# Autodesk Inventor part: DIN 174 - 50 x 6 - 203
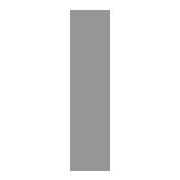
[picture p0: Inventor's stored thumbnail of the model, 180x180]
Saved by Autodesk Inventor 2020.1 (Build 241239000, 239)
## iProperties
IsCustomPart: 1
_CCFamilyMember: 200
_CCFamilyDisplayName: DIN EN 10278 - Flachstahl
_FrameMemberDoc: Frame Member File
_Version: 15.0.0
_GetPNFromCC: 1
Created: 2019-01
Part Number: DIN 174 - 50 x 6 - 203
Material: Stahl, weich
Description: Flachstahl
Document SubType Name: Modeling
Standard: DIN
Designer: lutzd
Standards Organization: DIN
Language: de-DE
Size Designation: 50 x 6
Categories: <MemberInstance><Categories><Category DisplayName="Profile" InternalName="089c4875-fa83-4c05-b084-43b9cc11f5ed" Mnemonic="GRDR"><CategoryParameter DisplayName="
Stock Number: 50 x 6
Mass: 470.279 g
Surface Area: 234.79 cm^2
Volume: 59.9082 cm^3
Density: 7.85 g/cm^3
Appearance: Semi-Polished(8)
G_L: 203,000 mm
G_W: 6,000 mm
G_H: 50,000 mm
DocNumber: ADSK-014329
Folder: .
Dimensions: 6x50x203 mm
Mass: 0,47 kg
Title: Profil-Bauteil
Author: lutzd
Revision Number: -
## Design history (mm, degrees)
node "Startebene"
node "Endebene"
sketch "Skizze"
  geometry: L1 (3, -25)-(-3, -25); L2 (-3, -25)-(-3, 25); L3 (-3, 25)-(3, 25); L4 (3, 25)-(3, -25); L5 (-6, 0)-(8, 0); L6 (0, -30)-(0, 40); L7 (0, 54)-(0, -44) reference; L8 (-9.2, 0)-(13.2, 0) reference
  constraints: 12 end point, 2 collinear, 2 parallel, 1 horizontal, 1 perpendicular
  dimensions: "d0" = 50 distance between parallel lines of L3 L1 (= G_W); "d1" = 6 distance between parallel lines of L4 L2 (= G_H); "d4" = 3 distance between parallel lines of L6 L4 (= 0.5 x d1); "d5" = 25 distance between parallel lines of L5 L3 (= 0.5 x d0)
extrude "Körper" new body sketch "Skizze" stored distance "d2" = 203 (= G_L); taper "d3" = 0 deg
node "Driven Length"
  sketch "Sketch3"
    geometry: L1 (0, 0)-(10, 0) reference
    constraints: 2 end point, 1 horizontal
  workplane "Work Plane3"
  sketch "Sketch4"
    geometry: L1 (-2, 0)-(12, 0) reference; L2 (-2, 203)-(12, 203) reference
    dimensions: "d9" = 203 distance between parallel lines of L1 L2 (derived)
sketch "Skizze5"
  geometry: L1 (177.75, -25)-(25.25, -25); L2 (0, -50)-(0, 0) reference; L3 (0, 0)-(203, 0) reference; 7 further points
  constraints: 3 coincident, 3 midpoint, 2 end point, 1 horizontal, 1 horizontal alignment, 1 vertical alignment
  dimensions: "d10" = 152.5 distance of L1.start L1.end
hole "Bohrung1" sketch "Skizze5" at (177.75, -25), (101.5, -25), (25.25, -25) diameter "d11" = 8.376; stored, may be unused: countersink angle "d15" = 90 deg, drill point angle "d17" = 118 deg; dims "d12" = 20, "d13" = 4, "d14" = 2, "d16" = 27.3
body "Solid1"
other parameters: "G_W" = 50 [user parameter; used in 1 equation term], "G_H" = 6 [user parameter; used in 1 equation term], "G_L" = 203 (= d9) [user parameter; used in 1 equation term], "G_OFFSET_START" = 0 [user parameter; used in 1 equation term], "G_OFFSET_END" = 0 [user parameter; used in 1 equation term], "d6" = 0 (computed from G_OFFSET_START), "d7" = 203 (= G_OFFSET_END + B_L), "B_L" = 203 [user parameter; used in 1 equation term], "d8" = 90 deg
